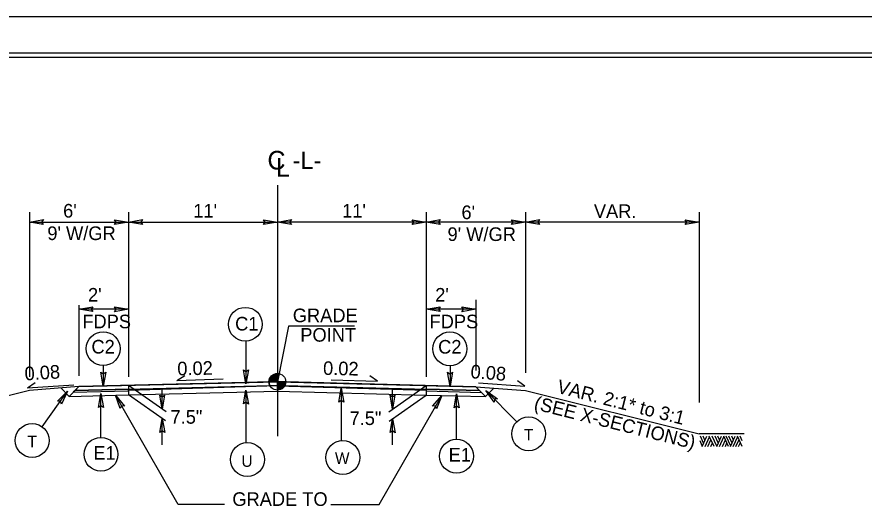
# Model space of a CAD drawing. Extents: x 573687 to 575553, y -54556 to -52223.
# Drawn here: x 574016 to 574539, y -52525 to -52223 of the extents above; entities that cross this region are included whole.
import ezdxf

# ---------------------------------------------------------------- set-up
doc = ezdxf.new("R2010")
doc.units = 0
for name, color, linetype in [('Old_Level_1', 7, 'Continuous'), ('Old_Level_35', 7, 'Continuous'), ('Prop Dimension', 7, 'Continuous'), ('Prop Dimension Text', 7, 'Continuous'), ('Sheet Cutting Line CELL', 7, 'Continuous'), ('Sheet Plot Border Inside CELL', 7, 'Continuous'), ('Sheet Plot Border Outside CELL', 7, 'Continuous'), ('Sheet Typical CELL', 7, 'Continuous'), ('Typical Arrow Superelevation CELL', 7, 'Continuous'), ('Typical Terminator CELL', 7, 'Continuous'), ('Typical Text Centerline CELL', 7, 'Continuous'), ('Typical Text Grade Point CELL', 7, 'Continuous'), ('Typical Text Label CELL', 7, 'Continuous')]:
    doc.layers.add(name, color=color, linetype=linetype)

msp = doc.modelspace()

# ---------------------------------------------------------------- linework, layer by layer
at = {"layer": 'Old_Level_1'}
for p, q in [((574054.59, -52450.97), (574176.99, -52447.97)), ((574157.49, -52448.45), (574054.59, -52450.97)), ((574171.8, -52448.1), (574157.74, -52448.44)), ((574176.99, -52447.97), (574171.8, -52448.1)), ((574176.99, -52447.97), (574299.39, -52451.09)), ((574177.6, -52447.99), (574176.99, -52447.97)), ((574176.99, -52448.09), (574176.99, -52447.97)), ((574179.16, -52450.28), (574176.99, -52448.09)), ((574176.99, -52448.09), (574179.16, -52450.28)), ((574176.99, -52448.82), (574176.99, -52448.09)), ((574176.99, -52448.09), (574176.99, -52448.09)), ((574176.99, -52448.82), (574178.42, -52450.26)), ((574178.42, -52450.26), (574176.99, -52448.82)), ((574176.99, -52448.82), (574176.99, -52449.56)), ((574176.99, -52450.22), (574176.99, -52448.82)), ((574176.99, -52448.82), (574176.99, -52448.82)), ((574178.36, -52448.01), (574177.6, -52447.99)), ((574177.6, -52447.99), (574179.91, -52450.3)), ((574179.91, -52450.3), (574177.6, -52447.99)), ((574180.67, -52450.32), (574178.36, -52448.01)), ((574179.12, -52448.03), (574178.36, -52448.01)), ((574178.36, -52448.01), (574180.67, -52450.32)), ((574179.85, -52448.05), (574179.12, -52448.03)), ((574179.12, -52448.03), (574181.41, -52450.34)), ((574181.41, -52450.34), (574179.12, -52448.03)), ((574181.77, -52449.94), (574179.85, -52448.05)), ((574180.6, -52448.07), (574179.85, -52448.05)), ((574179.85, -52448.05), (574181.77, -52449.94)), ((574181.96, -52449.39), (574180.6, -52448.07)), ((574182.16, -52448.1), (574180.6, -52448.07)), ((574180.6, -52448.07), (574181.96, -52449.39)), ((574299.39, -52451.09), (574182.16, -52448.1)), ((574023.99, -52453.26), (573944.4, -52473.16)), ((574054.59, -52450.97), (574023.99, -52453.26)), ((574043.42, -52451.8), (574048.59, -52456.97)), ((574054.59, -52450.97), (574048.59, -52456.97)), ((574051.1, -52454.46), (574085.19, -52453.63)), ((574052.28, -52453.28), (574177.04, -52450.22)), ((574052.28, -52453.28), (574172.37, -52450.34)), ((574054.59, -52450.97), (574052.28, -52453.28)), ((574085.19, -52450.22), (574085.19, -52456.07)), ((574176.99, -52450.49), (574085.19, -52453.28)), ((574085.19, -52456.07), (574177.13, -52453.82)), ((574172.37, -52450.34), (574176.99, -52450.22)), ((574176.84, -52453.82), (574268.79, -52456.16)), ((574176.93, -52450.22), (574301.7, -52453.4)), ((574176.99, -52449.56), (574177.67, -52450.24)), ((574176.99, -52449.56), (574176.99, -52450.22)), ((574177.67, -52450.24), (574176.99, -52449.56)), ((574176.99, -52450.22), (574177.67, -52450.24)), ((574176.99, -52450.49), (574268.79, -52453.21)), ((574177.67, -52450.24), (574178.42, -52450.26)), ((574178.42, -52450.26), (574179.16, -52450.28)), ((574179.16, -52450.28), (574179.91, -52450.3)), ((574179.91, -52450.3), (574180.67, -52450.32)), ((574180.67, -52450.32), (574181.41, -52450.34)), ((574181.41, -52450.34), (574181.58, -52450.34)), ((574181.58, -52450.34), (574301.7, -52453.4)), ((574268.79, -52450.31), (574268.79, -52456.16)), ((574268.79, -52453.66), (574302.82, -52454.52)), ((574299.39, -52451.09), (574329.99, -52453.38)), ((574299.39, -52451.09), (574305.39, -52457.09)), ((574301.7, -52453.4), (574299.39, -52451.09)), ((574310.56, -52451.93), (574305.39, -52457.09)), ((574329.99, -52453.38), (574437.06, -52480.15)), ((574048.59, -52456.97), (574085.19, -52456.07)), ((574268.79, -52456.16), (574305.39, -52457.09)), ((574464.99, -52480.15), (574437.06, -52480.15)), ((574439.06, -52487.46), (574437.68, -52484.51)), ((574439.84, -52485.8), (574437.89, -52481.6)), ((574438.89, -52487.86), (574441.78, -52481.6)), ((574440.67, -52483.99), (574439.6, -52481.6)), ((574440.76, -52487.86), (574443.52, -52481.89)), ((574442.54, -52487.86), (574444.43, -52483.79)), ((574446.31, -52487.86), (574443.4, -52481.6)), ((574444.3, -52487.86), (574445.31, -52485.69)), ((574448.02, -52487.68), (574445.2, -52481.6)), ((574448.92, -52485.73), (574447.02, -52481.6)), ((574447.95, -52487.86), (574450.84, -52481.6)), ((574449.73, -52483.92), (574448.68, -52481.6)), ((574449.66, -52487.86), (574452.43, -52481.91)), ((574451.46, -52487.86), (574453.33, -52483.79)), ((574455.23, -52487.86), (574452.29, -52481.6)), ((574453.28, -52487.86), (574454.23, -52485.75)), ((574456.65, -52487.65), (574453.83, -52481.6)), ((574457.48, -52485.85), (574455.53, -52481.6)), ((574456.55, -52487.86), (574459.43, -52481.58)), ((574458.36, -52483.97), (574457.27, -52481.6)), ((574458.1, -52487.86), (574460.9, -52481.79)), ((574459.82, -52487.86), (574461.75, -52483.6)), ((574463.74, -52487.86), (574460.84, -52481.6)), ((574461.46, -52487.86), (574462.58, -52485.39)), ((574463.74, -52484.51), (574462.4, -52481.6))]:
    msp.add_line(p, q, dxfattribs=at)
for points in [[(574157.74, -52448.44), (574157.61, -52449.16), (574157.49, -52448.45)], [(574176.99, -52447.97), (574176.99, -52448.09), (574176.99, -52448.09)], [(574176.99, -52448.09), (574176.99, -52448.82), (574176.99, -52448.82)], [(574176.99, -52448.09), (574176.99, -52448.09)], [(574176.99, -52448.82), (574176.99, -52448.82)]]:
    msp.add_lwpolyline(points, dxfattribs=at)
for start, end in [(181.4378, 207.1878), (181.4378, 207.1878), (332.7606, 358.5101), (337.6057, 344.0607), (344.0607, 358.5101), (332.7606, 337.6057)]:
    msp.add_arc((574176.98, -52447.97), 5.18, start, end, dxfattribs=at)
at = {"layer": 'Old_Level_35'}
for p, q in [((574176.99, -52447.37), (574173.64, -52444.02)), ((574176.99, -52446.63), (574174.03, -52443.71)), ((574176.99, -52445.9), (574174.49, -52443.43)), ((574176.99, -52445.16), (574175, -52443.17)), ((574176.99, -52444.44), (574175.55, -52442.99)), ((574176.99, -52443.71), (574176.13, -52442.85)), ((574176.99, -52442.97), (574176.8, -52442.81)), ((574176.99, -52447.97), (574176.99, -52442.79)), ((574176.99, -52447.97), (574171.8, -52447.97)), ((574172.46, -52447.97), (574171.84, -52447.35)), ((574173.2, -52447.97), (574171.96, -52446.73)), ((574173.92, -52447.97), (574172.12, -52446.17)), ((574174.65, -52447.97), (574172.35, -52445.67)), ((574175.39, -52447.97), (574172.61, -52445.21)), ((574176.13, -52447.97), (574172.92, -52444.77)), ((574176.84, -52447.97), (574173.25, -52444.37)), ((574176.99, -52453.16), (574176.99, -52447.97)), ((574182.15, -52447.97), (574176.99, -52447.97)), ((574176.99, -52448.09), (574180.58, -52451.71)), ((574176.99, -52448.82), (574180.19, -52452.03)), ((574177.58, -52447.97), (574180.93, -52451.32)), ((574178.32, -52447.97), (574181.25, -52450.9)), ((574179.06, -52447.97), (574181.53, -52450.46)), ((574179.78, -52447.97), (574181.78, -52449.95)), ((574180.51, -52447.97), (574181.97, -52449.4)), ((574181.25, -52447.97), (574182.08, -52448.82)), ((574181.99, -52447.97), (574182.15, -52448.13)), ((574176.99, -52449.56), (574179.75, -52452.33)), ((574176.99, -52450.3), (574179.29, -52452.61)), ((574176.99, -52451.04), (574178.78, -52452.84)), ((574176.99, -52451.75), (574178.23, -52453)), ((574176.99, -52452.49), (574177.61, -52453.11))]:
    msp.add_line(p, q, dxfattribs=at)
msp.add_circle((574176.98, -52447.97), 5.18, dxfattribs=at)
at = {"layer": 'Prop Dimension'}
for p, q in [((574176.99, -52326.59), (574176.99, -52481.6)), ((574023.99, -52343.21), (574023.99, -52445.01)), ((574085.19, -52343.21), (574085.19, -52445.01)), ((574268.79, -52343.21), (574268.79, -52445.01)), ((574329.99, -52343.21), (574329.99, -52442.37)), ((574437.06, -52343.21), (574437.06, -52460.83)), ((574023.99, -52349.35), (574085.19, -52349.35)), ((574085.19, -52349.35), (574176.99, -52349.35)), ((574268.79, -52349.35), (574176.99, -52349.35)), ((574329.99, -52349.35), (574268.79, -52349.35)), ((574437.06, -52349.35), (574329.99, -52349.35)), ((574054.59, -52400.7), (574054.59, -52444.21)), ((574299.39, -52397.47), (574299.39, -52440.98)), ((574085.19, -52403.19), (574054.59, -52403.19)), ((574299.39, -52403.19), (574268.79, -52403.19)), ((574157.61, -52422.91), (574157.61, -52449.16)), ((574069.61, -52437.98), (574069.61, -52450.69)), ((574283.46, -52438.03), (574283.46, -52450.74)), ((574031.84, -52475.72), (574047.62, -52453.79)), ((574105.93, -52464.79), (574105.93, -52452.57)), ((574157.54, -52453.06), (574157.55, -52485.51)), ((574216.37, -52451.88), (574216.37, -52484.34)), ((574248.04, -52464.89), (574248.04, -52452.66)), ((574324.63, -52472.63), (574305.65, -52453.39)), ((574068.16, -52482.29), (574068.16, -52455.27)), ((574115.87, -52523.8), (574077.15, -52456.27)), ((574239.73, -52523.8), (574278.38, -52456.41)), ((574287.5, -52483.48), (574287.5, -52455.45)), ((574105.93, -52486.81), (574105.93, -52470.65)), ((574248.04, -52486.9), (574248.04, -52470.74)), ((574144.31, -52523.8), (574115.87, -52523.8)), ((574209.86, -52523.8), (574239.73, -52523.8))]:
    msp.add_line(p, q, dxfattribs=at)
for points in [[(574108.35, -52466.49), (574085.19, -52450.22)], [(574245.63, -52466.58), (574268.79, -52450.31)], [(574108.01, -52472.1), (574085.19, -52456.07)], [(574245.97, -52472.2), (574268.79, -52456.16)]]:
    msp.add_lwpolyline(points, dxfattribs=at)
for centre in [(574157.23, -52412.46), (574069.53, -52427.52), (574283.38, -52427.58), (574331.97, -52480.07), (574068.16, -52492.74), (574158.48, -52495.92), (574217.3, -52494.75), (574287.5, -52493.94)]:
    msp.add_circle(centre, 10.46, dxfattribs=at)
at = {"layer": 'Prop Dimension Text'}
for p, q in [((574052.28, -52453.28), (574051.1, -52454.46)), ((574051.1, -52454.46), (574085.19, -52453.63)), ((574085.19, -52452.47), (574052.28, -52453.28)), ((574301.7, -52453.4), (574268.79, -52452.56)), ((574268.79, -52453.66), (574302.82, -52454.52)), ((574302.82, -52454.52), (574301.7, -52453.4))]:
    msp.add_line(p, q, dxfattribs=at)
for points in [[(574085.19, -52453.63), (574085.19, -52453.28), (574085.19, -52452.47)], [(574268.79, -52452.56), (574268.79, -52453.21), (574268.79, -52453.66)]]:
    msp.add_lwpolyline(points, dxfattribs=at)
msp.add_circle((574025.73, -52484.21), 10.46, dxfattribs=at)
at = {"layer": 'Sheet Cutting Line CELL'}
msp.add_line((575371.43, -52222.67), (573687.43, -52222.67), dxfattribs=at)
at = {"layer": 'Sheet Plot Border Inside CELL'}
msp.add_lwpolyline([(575366.93, -52245.12), (573700.43, -52245.12), (573700.43, -53300.22), (575366.93, -53300.22)], close=True, dxfattribs=at)
at = {"layer": 'Sheet Plot Border Outside CELL'}
msp.add_lwpolyline([(575371.43, -52222.67), (573687.43, -52222.67), (573687.43, -53322.67), (575371.43, -53322.67)], close=True, dxfattribs=at)
at = {"layer": 'Sheet Typical CELL'}
msp.add_lwpolyline([(575354.43, -52247.67), (573854.43, -52247.67), (573854.43, -53297.67), (575354.43, -53297.67)], close=True, dxfattribs=at)
at = {"layer": 'Typical Arrow Superelevation CELL'}
for p, q in [((574115.01, -52447.09), (574119.94, -52444.05)), ((574022.85, -52451.66), (574027.66, -52448.44)), ((574115.01, -52447.09), (574143.6, -52446.25)), ((574210.2, -52446.7), (574238.79, -52447.52)), ((574238.79, -52447.52), (574233.99, -52444.29)), ((574301.12, -52448.58), (574329.63, -52450.77)), ((574329.63, -52450.77), (574325, -52447.3)), ((574022.85, -52451.66), (574051.39, -52449.77))]:
    msp.add_line(p, q, dxfattribs=at)
at = {"layer": 'Typical Terminator CELL'}
for points in [[(574032.59, -52350.83), (574023.99, -52349.35), (574032.64, -52347.82), (574031.54, -52349.35)], [(574076.58, -52347.87), (574085.19, -52349.35), (574076.53, -52350.88), (574077.63, -52349.35)], [(574093.79, -52350.83), (574085.19, -52349.35), (574093.84, -52347.82), (574092.74, -52349.35)], [(574168.38, -52347.89), (574176.98, -52349.37), (574168.33, -52350.9), (574169.43, -52349.37)], [(574185.59, -52350.83), (574176.99, -52349.35), (574185.64, -52347.82), (574184.54, -52349.35)], [(574260.18, -52347.87), (574268.79, -52349.35), (574260.13, -52350.88), (574261.23, -52349.35)], [(574277.39, -52350.83), (574268.79, -52349.35), (574277.44, -52347.82), (574276.34, -52349.35)], [(574321.38, -52347.87), (574329.99, -52349.35), (574321.33, -52350.88), (574322.43, -52349.35)], [(574338.59, -52350.83), (574329.99, -52349.35), (574338.64, -52347.82), (574337.54, -52349.35)], [(574428.46, -52347.87), (574437.06, -52349.35), (574428.41, -52350.88), (574429.51, -52349.35)], [(574063.19, -52404.67), (574054.59, -52403.19), (574063.24, -52401.66), (574062.14, -52403.19)], [(574076.58, -52401.7), (574085.19, -52403.19), (574076.53, -52404.72), (574077.63, -52403.19)], [(574277.39, -52404.67), (574268.79, -52403.19), (574277.44, -52401.66), (574276.34, -52403.19)], [(574290.78, -52401.7), (574299.39, -52403.19), (574290.73, -52404.72), (574291.83, -52403.19)], [(574071.09, -52442.08), (574069.61, -52450.69), (574068.08, -52442.03), (574069.61, -52443.13)], [(574159.1, -52440.56), (574157.61, -52449.16), (574156.08, -52440.51), (574157.61, -52441.61)], [(574284.95, -52442.13), (574283.46, -52450.74), (574281.93, -52442.09), (574283.46, -52443.19)], [(574041.39, -52459.91), (574047.62, -52453.79), (574043.81, -52461.7), (574043.21, -52459.92)], [(574156.06, -52461.66), (574157.54, -52453.06), (574159.07, -52461.71), (574157.54, -52460.61)], [(574214.88, -52460.49), (574216.37, -52451.88), (574217.9, -52460.54), (574216.37, -52459.44)], [(574310.64, -52460.56), (574305.65, -52453.39), (574312.82, -52458.48), (574310.96, -52458.77)], [(574066.68, -52463.87), (574068.16, -52455.27), (574069.69, -52463.92), (574068.16, -52462.82)], [(574080.08, -52464.5), (574077.15, -52456.27), (574082.72, -52463.06), (574080.85, -52462.85)], [(574107.41, -52456.19), (574105.93, -52464.79), (574104.4, -52456.14), (574105.93, -52457.24)], [(574249.52, -52456.28), (574248.04, -52464.89), (574246.51, -52456.23), (574248.04, -52457.33)], [(574272.66, -52463.01), (574278.38, -52456.41), (574275.21, -52464.61), (574274.47, -52462.87)], [(574286.02, -52464.05), (574287.5, -52455.45), (574289.03, -52464.1), (574287.5, -52463)], [(574104.45, -52479.25), (574105.93, -52470.65), (574107.46, -52479.3), (574105.93, -52478.2)], [(574246.56, -52479.39), (574248.04, -52470.78), (574249.57, -52479.43), (574248.04, -52478.33)]]:
    msp.add_lwpolyline(points, close=True, dxfattribs=at)
at = {"layer": 'Typical Text Grade Point CELL'}
msp.add_lwpolyline([(574224.64, -52413.65), (574183.93, -52413.65), (574176.99, -52447.97)], dxfattribs=at)

# ---------------------------------------------------------------- texts
at = {"layer": 'Prop Dimension'}
msp.add_text("11'", height=8.415, rotation=359.9999, dxfattribs=at).set_placement((574216.91, -52346.57))
at = {"layer": 'Prop Dimension Text'}
for s, rotation, p in [(" 6'", 0.0001, (574041.7, -52346.57)), ("11'", 0.0001, (574125.11, -52346.57)), (" 6'", 359.9999, (574287.39, -52347.54)), ('VAR.', 359.9999, (574372.21, -52346.81)), ("9' W/GR", 0.0001, (574035.08, -52360.46)), ("9' W/GR", 359.9999, (574281.94, -52361.03)), (" 2'", 359.9999, (574057.02, -52398.48)), (" 2'", 359.9999, (574271.19, -52398.48)), ('FDPS', 359.9999, (574056.69, -52414.95)), ('FDPS', 359.9999, (574270.85, -52414.95)), ('C1', 0.0001, (574150.91, -52416.31)), ('C2', 0.0001, (574062.29, -52430.52)), ('C2', 0.0001, (574276.14, -52430.58)), ('7.5"', 0.0001, (574111.07, -52473.87)), ('7.5"', 0.0001, (574221.5, -52474.67)), ('E1', 0.0001, (574063.46, -52496.07)), ('E1', 0.0001, (574282.61, -52497.23))]:
    msp.add_text(s, height=8.415, rotation=rotation, dxfattribs=at).set_placement(p)
for s, p in [('T', (574329.07, -52484.23)), ('T', (574022.83, -52488.36)), ('U', (574154.82, -52500.5)), ('W', (574212.49, -52498.7))]:
    msp.add_text(s, height=7.11, dxfattribs=at).set_placement(p)
at = {"layer": 'Typical Text Centerline CELL'}
for s, height, p in [('C', 11.53, (574170.85, -52316.93)), ('-L-', 10.808, (574186.44, -52316.62)), ('L', 11.53, (574176.08, -52321.26))]:
    msp.add_text(s, height=height, rotation=0.0001, dxfattribs=at).set_placement(p)
at = {"layer": 'Typical Text Grade Point CELL'}
for s, p in [('GRADE ', (574186.49, -52411.18)), ('POINT', (574191.12, -52423.2))]:
    msp.add_text(s, height=8.415, rotation=0.0001, dxfattribs=at).set_placement(p)
at = {"layer": 'Typical Text Label CELL'}
for s, rotation, p in [(' 0.08', 3.4327, (574018.17, -52447.36)), (' 0.02', 1.1917, (574112.21, -52444.11)), (' 0.02', 358.8083, (574201.97, -52443.64)), (' 0.08', 355.6177, (574292.76, -52445.47)), ('VAR. 2:1* to 3:1', 345.6447, (574348.86, -52454.64)), ('(SEE X-SECTIONS)', 345.8737, (574334.77, -52464.82)), ('GRADE TO ', 0.0001, (574149.2, -52524.63))]:
    msp.add_text(s, height=8.415, rotation=rotation, dxfattribs=at).set_placement(p)

doc.saveas('drawing.dxf')
